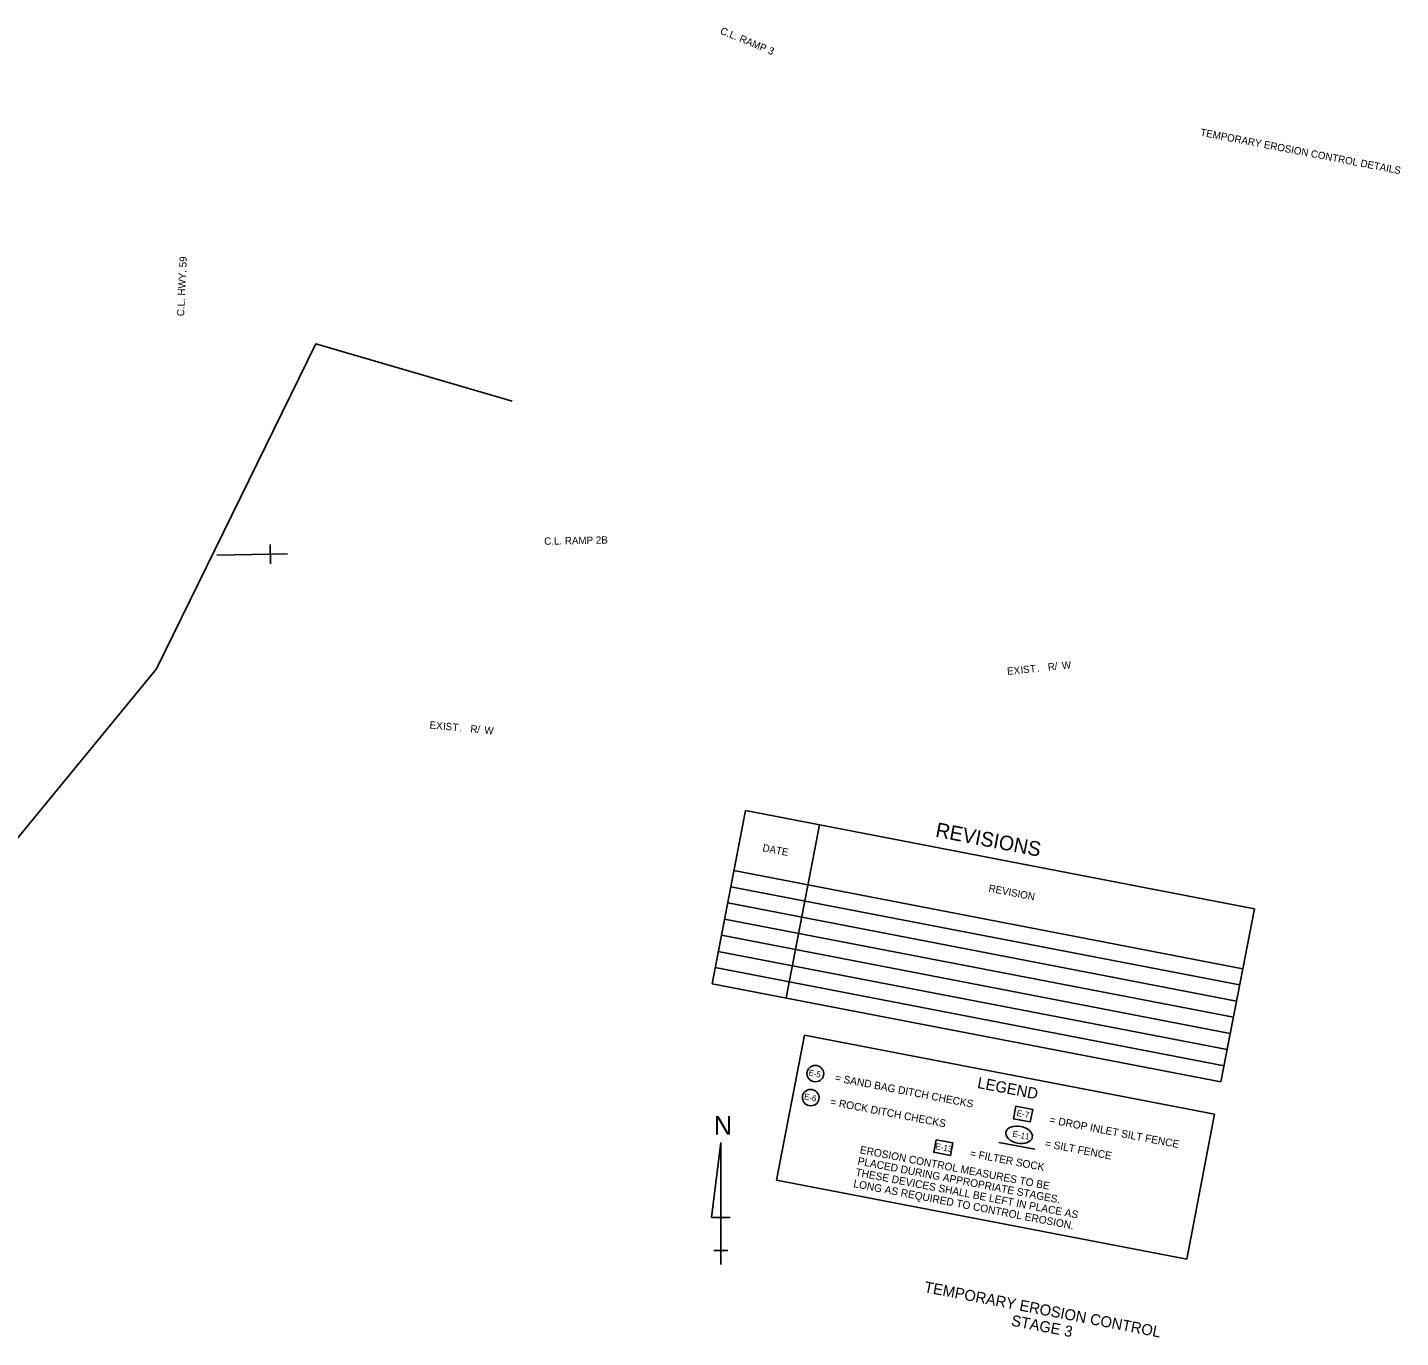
# Model space of a CAD drawing. Extents: x 607205 to 611709, y 416008 to 419672.
# Drawn here: x 610583 to 611709, y 418577 to 419651 of the extents above; entities that cross this region are included whole.
import ezdxf

# ---------------------------------------------------------------- set-up
doc = ezdxf.new("R2010")
doc.units = 0
for name, color, linetype in [('Default', 7, 'Continuous'), ('R_Draft', 7, 'Continuous'), ('R_Horz Alg', 7, 'Continuous'), ('R_Horz Alg Stationing', 7, 'Continuous'), ('R_Island', 7, 'Continuous'), ('S_DRIVEWAY', 7, 'Continuous'), ('S_SIGN', 7, 'Continuous'), ('X_Phi Angle_SB', 7, 'Continuous')]:
    doc.layers.add(name, color=color, linetype=linetype)

msp = doc.modelspace()

# ---------------------------------------------------------------- linework, layer by layer
at = {"layer": 'R_Draft'}
for points in [[(610980.3, 419345), (610819.3, 419392), (610688.6, 419125.7)], [(610688.6, 419125.7), (610502.4, 418898.9), (610114, 418761.3)]]:
    msp.add_lwpolyline(points, dxfattribs=at)
at = {"layer": 'R_Horz Alg'}
msp.add_line((610738.1, 419218.8), (610796, 419220), dxfattribs=at)
at = {"layer": 'R_Horz Alg Stationing'}
msp.add_lwpolyline([(610781.8, 419227.7), (610782.1, 419211.7)], dxfattribs=at)
at = {"layer": 'S_DRIVEWAY'}
for p, q in [((611144.3, 418867.5), (611171.7, 419009.4)), ((611171.7, 419009.4), (611589, 418928.8)), ((611232.3, 418997.7), (611205, 418855.8)), ((611162.2, 418960.3), (611579.5, 418879.7)), ((611159.6, 418947), (611576.9, 418866.5)), ((611157.1, 418933.8), (611574.4, 418853.2)), ((611589, 418928.8), (611561.6, 418786.9)), ((611154.5, 418920.5), (611571.8, 418840)), ((611154.5, 418920.5), (611571.8, 418840)), ((611151.9, 418907.3), (611569.2, 418826.7)), ((611149.4, 418894), (611566.7, 418813.5)), ((611146.8, 418880.8), (611564.1, 418800.2)), ((611561.6, 418786.9), (611144.3, 418867.5)), ((611197.1, 418706.5), (611220, 418825.4)), ((611220, 418825.4), (611556.4, 418760.4)), ((611556.4, 418760.4), (611533.5, 418641.6)), ((611151.4, 418737.2), (611143.7, 418675.7)), ((611151.4, 418637.2), (611151.4, 418737.2)), ((611151.4, 418737.2), (611151.4, 418660.3)), ((611533.5, 418641.6), (611197.1, 418706.5)), ((611143.7, 418675.7), (611159.1, 418675.7)), ((611151.4, 418637.2), (611151.4, 418660.3)), ((611151.4, 418648.7), (611145.7, 418648.7)), ((611145.7, 418648.7), (611157.2, 418648.7)), ((611151.4, 418637.2), (611151.4, 418648.7))]:
    msp.add_line(p, q, dxfattribs=at)
for points in [[(611393.4, 418767.1), (611407.2, 418764.4), (611405.2, 418754.1), (611391.4, 418756.8)], [(611328.1, 418739.6), (611341.8, 418737), (611339.8, 418726.7), (611326.1, 418729.3)]]:
    msp.add_lwpolyline(points, close=True, dxfattribs=at)
for centre, major_axis, ratio in [((611229, 418793.8), (-6.76, 1.31), 0.97521), ((611225.2, 418774.1), (-6.76, 1.31), 0.97521), ((611396.1, 418743.6), (10.8, -2.1), 0.638788)]:
    msp.add_ellipse(centre, major_axis=major_axis, ratio=ratio, dxfattribs=at)
at = {"layer": 'S_SIGN'}
msp.add_lwpolyline([(611379.5, 418737.4), (611409, 418731.7)], dxfattribs=at)

# ---------------------------------------------------------------- texts
at = {"layer": 'Default'}
for s, rotation, p in [('C.L. RAMP 3', 337.5734, (611150.4, 419646.5)), ('C.L. HWY. 59', 87.2385, (610711.3, 419414.6)), ('C.L. RAMP 2B', 1.1692, (611006.7, 419227.3))]:
    msp.add_text(s, height=6, rotation=rotation, dxfattribs=at).set_placement(p)
at = {"layer": 'R_Draft'}
for s, rotation, p in [('R', 5.9666, (611419.9, 419124.1)), ('/', 5.9666, (611425.5, 419124.7)), ('W', 5.9666, (611431.4, 419125.3)), ('E', 5.9666, (611386.5, 419120.6)), ('X', 5.9666, (611391.9, 419121.1)), ('I', 5.9666, (611397.6, 419121.7)), ('S', 5.9666, (611399.6, 419121.9)), ('T', 5.9666, (611405.2, 419122.5)), ('.', 5.9666, (611411, 419123.1)), ('E', 354.5081, (610912.4, 419076.8)), ('X', 354.5081, (610917.8, 419076.3)), ('I', 354.5081, (610923.5, 419075.7)), ('S', 354.5081, (610925.5, 419075.6)), ('T', 354.5081, (610931.2, 419075)), ('.', 354.5081, (610937, 419074.5)), ('R', 354.5081, (610945.9, 419073.6)), ('/', 354.5081, (610951.5, 419073.1)), ('W', 354.5081, (610957.3, 419072.5))]:
    msp.add_text(s, height=6, rotation=rotation, dxfattribs=at).set_placement(p)
at = {"layer": 'R_Island'}
for s, height, p in [('TEMPORARY EROSION CONTROL DETAILS', 6, (611544.3, 419562.8)), ('TEMPORARY EROSION CONTROL ', 9, (611317.7, 418614.7)), ('STAGE 3', 9, (611389.1, 418587.2))]:
    msp.add_text(s, height=height, rotation=349.0745, dxfattribs=at).set_placement(p)
at = {"layer": 'S_DRIVEWAY'}
for s, height, rotation, p in [('REVISIONS', 12, 349.0745, (611326.9, 418988.1)), ('DATE', 6, 349.0745, (611185.3, 418976.2)), ('REVISION', 6, 349.0745, (611370.7, 418943)), ('E-5', 4.88, 349.0745, (611223.1, 418792.4)), ('= SAND BAG DITCH CHECKS', 6.25, 349.0745, (611244.6, 418787.6)), ('LEGEND', 9.14, 349.0745, (611361.3, 418782.1)), ('E-6', 4.88, 349.0745, (611219.4, 418772.8)), ('= ROCK DITCH CHECKS', 6.25, 349.0745, (611240.8, 418767.9)), ('N', 15.4, 360, (611145.8, 418743.6)), ('E-7', 5, 348.6922, (611393.7, 418759.2)), ('E-13', 5, 348.6922, (611327, 418732)), ('E-11', 5, 349.0745, (611390.3, 418742.2)), ('PLACED DURING APPROPRIATE STAGES. ', 6.25, 349.0745, (611263.3, 418719.3)), ('EROSION CONTROL MEASURES TO BE', 6.25, 349.0745, (611265.1, 418728.5)), ('THESE DEVICES SHALL BE LEFT IN PLACE AS ', 6.25, 349.0745, (611261.5, 418710.1)), ('LONG AS REQUIRED TO CONTROL EROSION.', 6.25, 349.0745, (611259.8, 418700.8))]:
    msp.add_text(s, height=height, rotation=rotation, dxfattribs=at).set_placement(p)
at = {"layer": 'X_Phi Angle_SB'}
for s, p in [('= DROP INLET SILT FENCE', (611420.7, 418753.1)), ('= SILT FENCE', (611416.9, 418733.7)), ('= FILTER SOCK', (611355.3, 418725.6))]:
    msp.add_text(s, height=6.25, rotation=349.0745, dxfattribs=at).set_placement(p)

doc.saveas('drawing.dxf')
